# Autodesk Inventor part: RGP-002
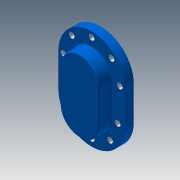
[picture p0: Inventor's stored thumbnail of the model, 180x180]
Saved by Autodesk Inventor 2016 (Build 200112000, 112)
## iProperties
Created: 2013-11
Part Number: RGP-002
Material: Aluminum 6061
Document SubType Name: Modeling
Designer: normanpa
Density: 2.71 g/cm^3
Appearance: 0,128,255
Description: BACK COVER
Mass: 1044.06 g
Surface Area: 628.614 cm^2
Volume: 385.262 cm^3
Author: Autodesk
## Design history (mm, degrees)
workplane "Work Plane1"
sketch "Sketch1"
  geometry: L1 (-60, 55.151)-(-60, -4.849); L2 (60, -4.849)-(60, 55.151); C1 r 5 at (-47, -4.849); C2 r 5 at (50.721, 55.151) reference; C3 r 5 at (50.721, 55.151) reference; A1 r 60 centre (0, 55.151) between (60, 55.151) and (-60, 55.151); A2 r 60 centre (0, -4.849) between (-60, -4.849) and (60, -4.849); 1 further point
  constraints: 5 centre point, 4 end point, 4 point on circle, 4 other
extrude "Extrusion1" new body sketch "Sketch1" distance "d0" = 16; taper "d1" = 0 deg
sketch "Sketch2"
  geometry: L1 (-60, 55.151)-(-60, -4.849) reference; L2 (60, -4.849)-(60, 55.151) reference; L3 (35, 55.151)-(35, -4.849); L4 (-35, -4.849)-(-35, 55.151); A1 r 60 centre (0, 55.151) between (60, 55.151) and (-60, 55.151) reference; A2 r 60 centre (0, -4.849) between (-60, -4.849) and (60, -4.849) reference; A3 r 35 centre (0, 55.151) between (35, 55.151) and (-35, 55.151); A4 r 35 centre (0, -4.849) between (-35, -4.849) and (35, -4.849); 1 further point
  constraints: 4 end point, 4 point on circle, 2 centre point, 3 other
  dimensions: "d2" = 35 radius of A3
extrude "Extrusion2" join sketch "Sketch2" distance "d3" = 22; taper "d4" = 0 deg
fillet "Fillet1" dims "d5" = 2
hole "Hole1" sketch "Sketch1" diameter "d6" = 10; stored, may be unused: countersink angle "d10" = 90 deg, drill point angle "d12" = 118 deg; dims "d7" = 6, "d8" = 4, "d9" = 2, "d11" = 8
hole "Hole2" sketch "Sketch1" diameter "d13" = 10; stored, may be unused: countersink angle "d17" = 90 deg, drill point angle "d19" = 118 deg; dims "d14" = 6, "d15" = 4, "d16" = 2, "d18" = 8
pattern_circular "Circular Pattern1" dims angle "d21" = 180 deg
pattern_circular "Circular Pattern2" dims angle "d24" = 180 deg
node "Sketch3"
hole "Hole3" diameter "d26" = 35; stored, may be unused: countersink angle "d30" = 90 deg, drill point angle "d32" = 0 deg; dims "d27" = 6, "d28" = 4, "d29" = 2, "d31" = 30, "d47" = 10, "d48" = 10
hole "Hole4" diameter "d35" = 40; stored, may be unused: countersink angle "d39" = 90 deg, drill point angle "d41" = 0 deg; dims "d36" = 6, "d37" = 4, "d38" = 2, "d40" = 30, "d44" = 10, "d45" = 10
fillet "Fillet2" dims "d46" = 2
body "Solid1"
